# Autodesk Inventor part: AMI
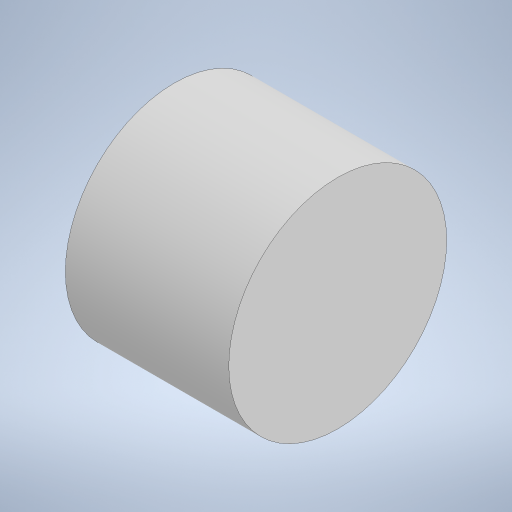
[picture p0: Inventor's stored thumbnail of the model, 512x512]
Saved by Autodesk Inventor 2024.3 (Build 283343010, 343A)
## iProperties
Created: 2025-07
Part Number: AMI
Material: 一般
Document SubType Name: Modeling
Designer: kouki
Density: 1 g/cm^3
Appearance: 既定
Author: kouki
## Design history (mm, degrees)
sketch "スケッチ1"
  geometry: C1 r 200 at (0, 0); 1 further point
  constraints: 1 centre point, 1 coincident
  dimensions: "d0" = 400 diameter of C1
extrude "押し出し1" new body sketch "スケッチ1" stored distance "d1" = 300; taper "d2" = 0 deg
node "ソリッド1"
